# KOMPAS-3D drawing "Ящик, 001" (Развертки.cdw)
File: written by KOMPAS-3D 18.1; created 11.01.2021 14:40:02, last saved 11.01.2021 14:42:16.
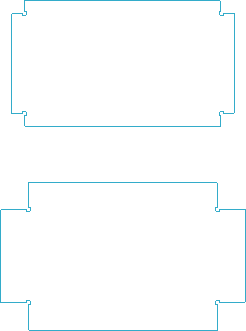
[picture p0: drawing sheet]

Sheet 1: A3, landscape

Document properties: Масса: 0.424246; Наименование: Ящик; Полное имя файла: 001 - Ящик.m3d

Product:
- Part/product: Ящик  | designation 001
    Масса: 0.424246
    source file: Развертки.cdw

Title block, sheet 1: scale: 1:1; Количество листов документа: 1; Форматы листов документа: A3

Views: Вид 1, Развертка, Вид 2
Referenced files in D:\Временные файлы КОМПАСа\Ящик_мойки\: 001 - Ящик.m3d, 002 - Крышка.m3d
Referenced files in D:\Ящик\: 002 - Крышка.m3d, 001 - Ящик.m3d
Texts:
  Без оформления
  Крышка
  Ящик
Dimensions and other numbers on the sheet: 001; 002; 1:1; 1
